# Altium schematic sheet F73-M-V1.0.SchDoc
size A3
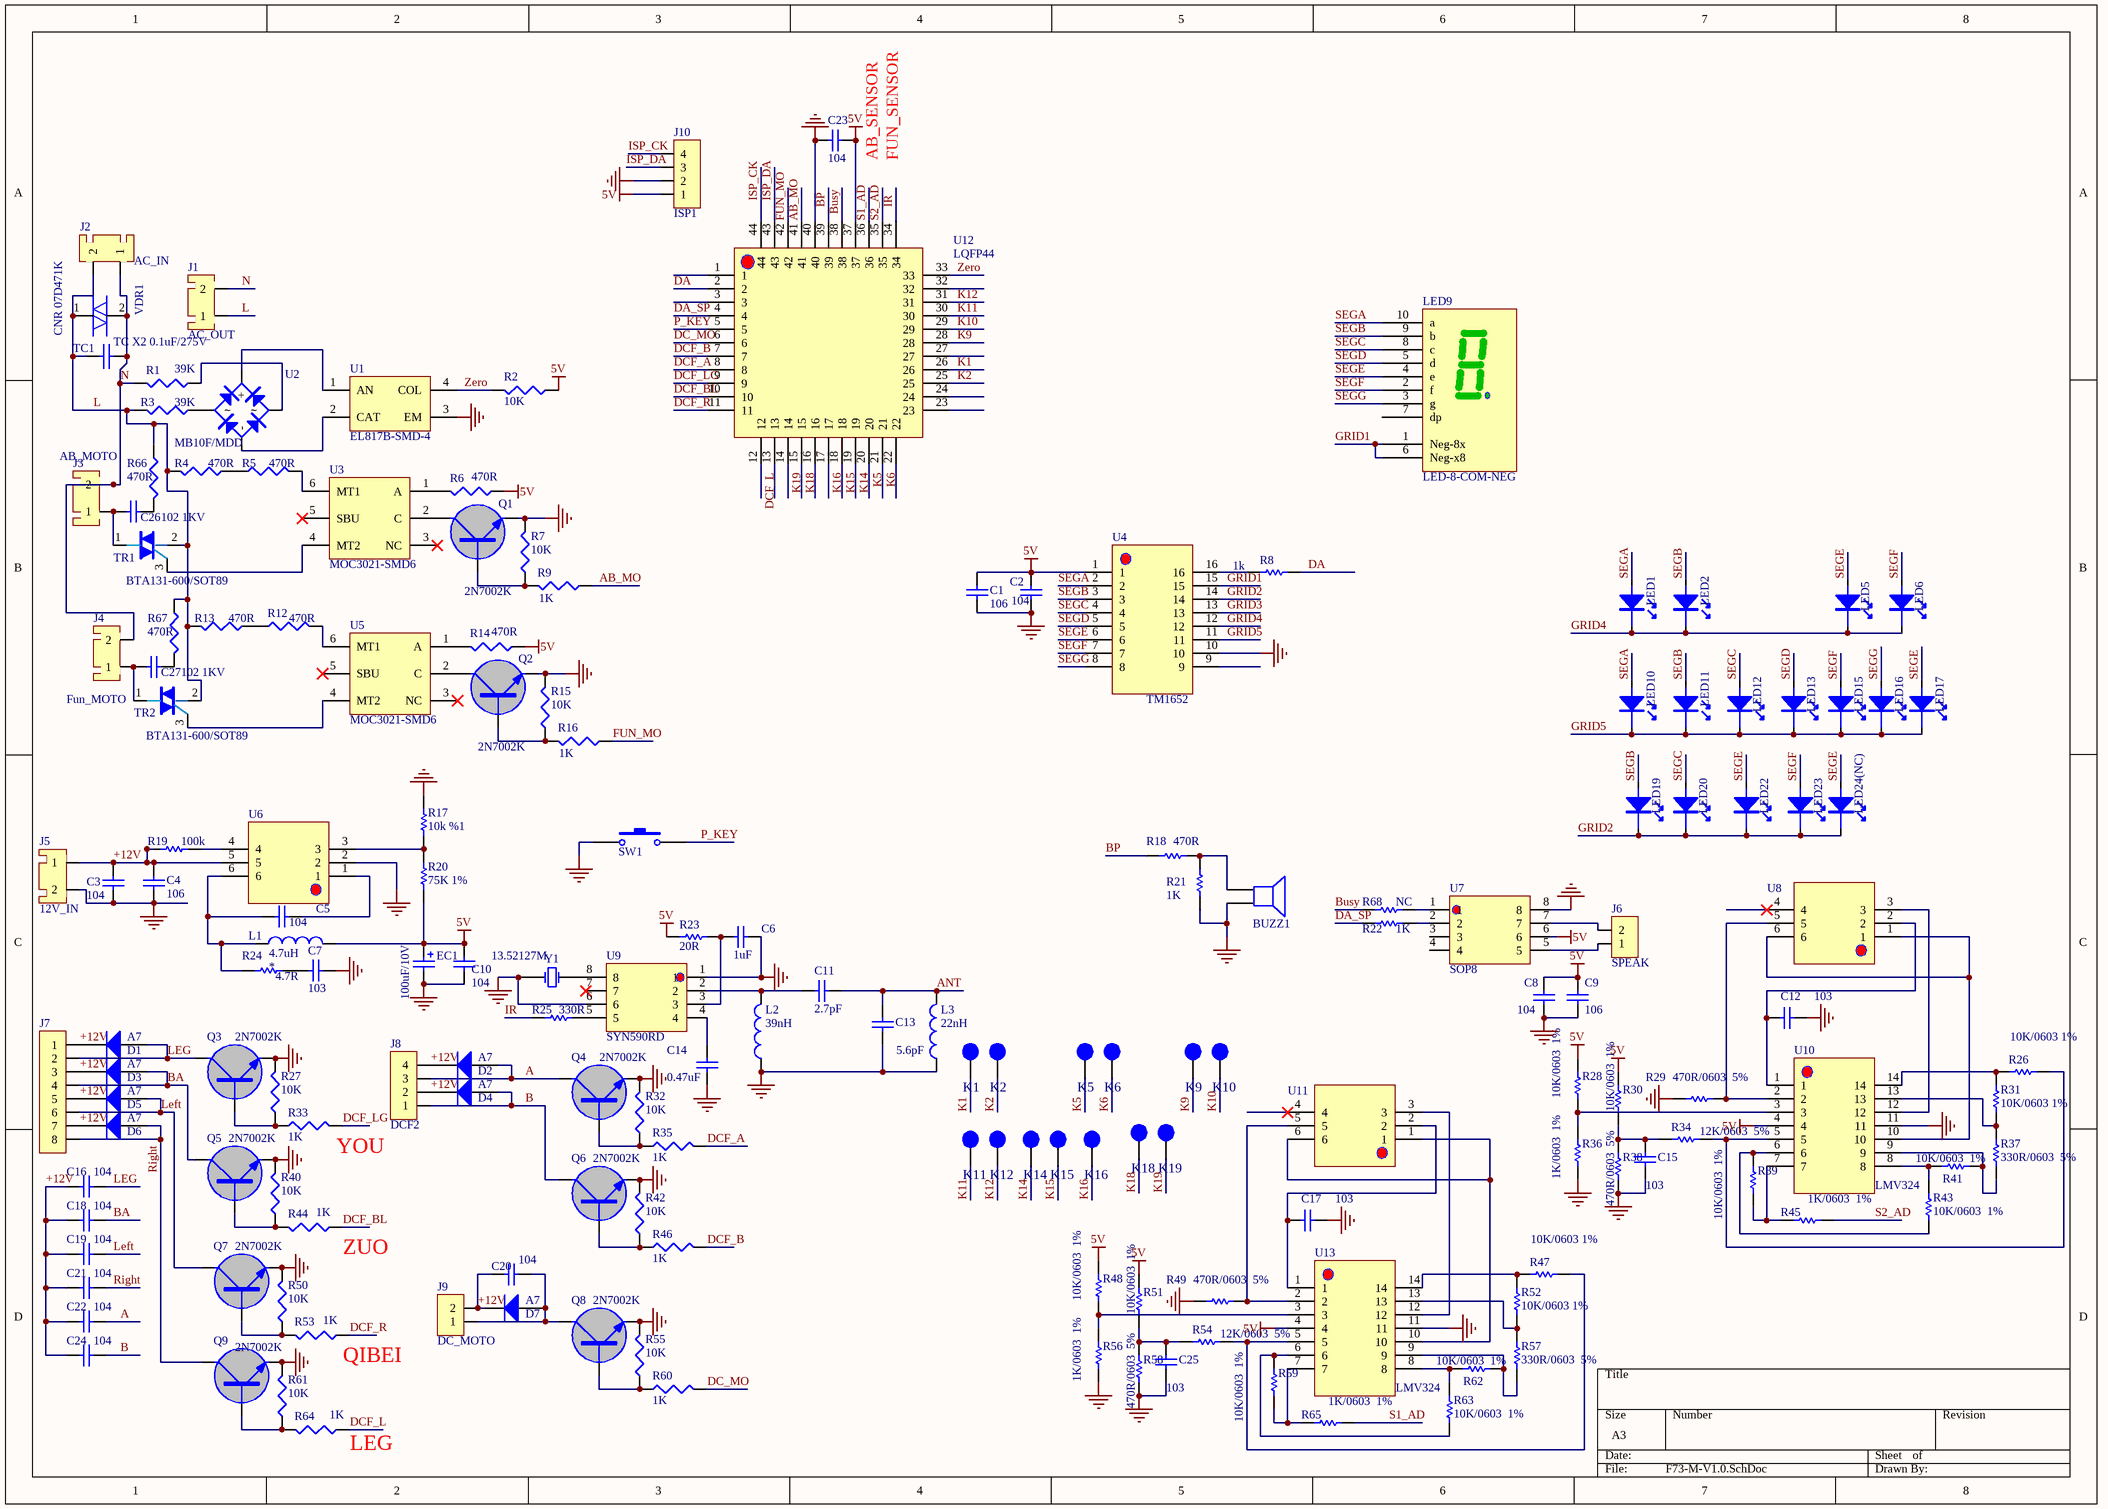
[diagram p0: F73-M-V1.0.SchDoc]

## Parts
BUZZ1  Speaker  [BUZ-1407-7.5]  (value not drawn)
C1  106  [0805C]
C2  104  [0603C]
C3  104  [0603C]
C4  106  [0805C]
C5  104  [0603C]
C6  1uF  [0603C]
C7  103  [0603C]
C8  104  [0603C]
C9  106  [0805C]
C10  104  [0603C]
C11  2.7pF  [0603C]
C12  103  [0603C]
C13  5.6pF  [0603C]
C14  0.47uF  [0603C]
C15  103  [0603C]
C16  104  [0603C]
C17  103  [0603C]
C18  104  [0603C]
C19  104  [0603C]
C20  104  [0603C]
C21  104  [0603C]
C22  104  [0603C]
C23  104  [0603C]
C24  104  [0603C]
C25  103  [0603C]
C26  102 1KV  [1206C]
C27  102 1KV  [1206C]
D1  A7  [SOD-123FL_L2.8-W1.8-LS3.7]
D2  A7  [SOD-123FL_L2.8-W1.8-LS3.7]
D3  A7  [SOD-123FL_L2.8-W1.8-LS3.7]
D4  A7  [SOD-123FL_L2.8-W1.8-LS3.7]
D5  A7  [SOD-123FL_L2.8-W1.8-LS3.7]
D6  A7  [SOD-123FL_L2.8-W1.8-LS3.7]
D7  A7  [SOD-123FL_L2.8-W1.8-LS3.7]
EC1  100uF/10V  [CAP SMD 6.3*5.5mm]
J1  AC_OUT  [K-VH3.96-3P]
J2  AC_IN  [K-VH3.96-3P]
J3  AB_MOTO  [K-VH3.96-3P]
J4  Fun_MOTO  [K-VH3.96-3P]
J5  12V_IN  [CON2-SMD-XHB 2*2.5MM]
J6  SPEAK  [CON2-SMD_PH2.0-1X2PW]
J7  (no value)  [CON8-SMD-XHB 8*2.5MM]
J8  DCF2  [CON4-SMD_4P-P2.54_XH2.54-4AB]
J9  DC_MOTO  [CON2-SMD-XHB 2*2.5MM]
J10  ISP1  [CON4 -2.54-H]
K1  Φ15 H8mm弹簧  [TK_HF-13*13*8]  (value not drawn)
K2  Φ15 H8mm弹簧  [TK_HF-13*13*8]  (value not drawn)
K5  Φ15 H8mm弹簧  [TK_HF-13*13*8]  (value not drawn)
K6  Φ15 H8mm弹簧  [TK_HF-13*13*8]  (value not drawn)
K9  Φ15 H8mm弹簧  [TK_HF-13*13*8]  (value not drawn)
K10  Φ15 H8mm弹簧  [TK_HF-13*13*8]  (value not drawn)
K11  Φ15 H8mm弹簧  [TK_HF-13*13*8]  (value not drawn)
K12  Φ15 H8mm弹簧  [TK_HF-13*13*8]  (value not drawn)
K14  Φ15 H8mm弹簧  [TK_HF-13*13*8]  (value not drawn)
K15  Φ15 H8mm弹簧  [TK_HF-13*13*8]  (value not drawn)
K16  Φ15 H8mm弹簧  [TK_HF-13*13*8]  (value not drawn)
K18  Φ15 H8mm弹簧  [TK_HF-13*13*8]  (value not drawn)
K19  Φ15 H8mm弹簧  [TK_HF-13*13*8]  (value not drawn)
L1  4.7uH  [INDC5050]
L2  39nH  [0603R]
L3  22nH  [0603R]
LED1  LED_0603  [LED_0603]  (value not drawn)
LED2  LED_0603  [LED_0603]  (value not drawn)
LED5  LED_0603  [LED_0603]  (value not drawn)
LED6  LED_0603  [LED_0603]  (value not drawn)
LED9  LED-8-COM-NEG  [LED1B-10P(7.5*14*H8.5 P2.54*10.16)]
LED10  LED_0603  [LED_0603]  (value not drawn)
LED11  LED_0603  [LED_0603]  (value not drawn)
LED12  LED_0603  [LED_0603]  (value not drawn)
LED13  LED_0603  [LED_0603]  (value not drawn)
LED15  LED_0603  [LED_0603]  (value not drawn)
LED16  LED_0603  [LED_0603]  (value not drawn)
LED17  LED_0603  [LED_0603]  (value not drawn)
LED19  LED_0603  [LED_0603]  (value not drawn)
LED20  LED_0603  [LED_0603]  (value not drawn)
LED22  LED_0603  [LED_0603]  (value not drawn)
LED23  LED_0603  [LED_0603]  (value not drawn)
LED24(NC)  LED_0603  [LED_0603]  (value not drawn)
Q1  2N7002K  [SOT-23 - MOS]
Q2  2N7002K  [SOT-23 - MOS]
Q3  2N7002K  [SOT-23 - MOS]
Q4  2N7002K  [SOT-23 - MOS]
Q5  2N7002K  [SOT-23 - MOS]
Q6  2N7002K  [SOT-23 - MOS]
Q7  2N7002K  [SOT-23 - MOS]
Q8  2N7002K  [SOT-23 - MOS]
Q9  2N7002K  [SOT-23 - MOS]
R1  39K  [1206R]
R2  10K  [0603]
R3  39K  [1206R]
R4  470R  [1206R]
R5  470R  [1206R]
R6  470R  [0603]
R7  10K  [0603]
R8  1k  [0603R]
R9  1K  [0603]
R12  470R  [1206R]
R13  470R  [1206R]
R14  470R  [0603]
R15  10K  [0603]
R16  1K  [0603]
R17  10k %1  [0603R]
R18  470R  [0603R]
R19  100k  [0603R]
R20  75K 1%  [0603R]
R21  1K  [0603R]
R22  1K  [0603R]
R23  20R  [0603R]
R24  4.7R  [0603R]
R25  330R  [0603R]
R26  10K/0603 1%  [0603R]
R27  10K  [0603]
R28  10K/0603  1%  [0603R]
R29  470R/0603  5%  [0603R]
R30  10K/0603  1%  [0603R]
R31  10K/0603 1%  [0603R]
R32  10K  [0603]
R33  1K  [0603]
R34  12K/0603  5%  [0603R]
R35  1K  [0603]
R36  1K/0603  1%  [0603R]
R37  330R/0603  5%  [0603R]
R38  470R/0603  5%  [0603R]
R39  10K/0603  1%  [0603R]
R40  10K  [0603]
R41  10K/0603  1%  [0603R]
R42  10K  [0603]
R43  10K/0603  1%  [0603R]
R44  1K  [0603]
R45  1K/0603  1%  [0603R]
R46  1K  [0603]
R47  10K/0603 1%  [0603R]
R48  10K/0603  1%  [0603R]
R49  470R/0603  5%  [0603R]
R50  10K  [0603]
R51  10K/0603  1%  [0603R]
R52  10K/0603 1%  [0603R]
R53  1K  [0603]
R54  12K/0603  5%  [0603R]
R55  10K  [0603]
R56  1K/0603  1%  [0603R]
R57  330R/0603  5%  [0603R]
R58  470R/0603  5%  [0603R]
R59  10K/0603  1%  [0603R]
R60  1K  [0603]
R61  10K  [0603]
R62  10K/0603  1%  [0603R]
R63  10K/0603  1%  [0603R]
R64  1K  [0603]
R65  1K/0603  1%  [0603R]
R66  470R  [1206R]
R67  470R  [1206R]
R68  NC  [0603R]
SW1  SW-PB  [BUTTON-SMD-6*6*10]  (value not drawn)
TC1  TC X2 0.1uF/275V  [CAP-TH_L13.0-W6.0-P10.00-D0.6]
TR1  BTA131-600/SOT89  [SOT-89 BT131-600]
TR2  BTA131-600/SOT89  [SOT-89 BT131-600]
U1  EL817B-SMD-4  [PC817-smd]
U2  MB10F/MDD  [DB-MB10F]
U3  MOC3021-SMD6  [SMD6]
U4  TM1652  [SOP16(150MIL)]
U5  MOC3021-SMD6  [SMD6]
U6  HT7712  [SOT23-6_M]  (value not drawn)
U7  SOP8  [SOP8-SS]
U8  SOP6  [PSG010R/S]  (value not drawn)
U9  SYN590RD  [SOP8(5.1*6.2mm)]
U10  LMV324  [SOP14(150mil)]
U11  SOP6  [PSG010R/S]  (value not drawn)
U12  LQFP44  [LQFP44]
U13  LMV324  [SOP14(150mil)]
VDR1  CNR 07D471K  [RES-TH_L9.0-W5.0-P5-D0.7-S3.00]
Y1  13.52127M  [HC-49S_L11.4-W4.8]

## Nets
5V: C1.2 C2.2 C8.1 C9.1 C10.1 C23.1 EC1.1 J10.1 L1.2 R2.1 R6.1 R14.1 R20.1 R23.1 R28.1 R30.1 R48.1 R51.1 U4.1 U7.6 U10.4 U12.37 U13.4
GND: BUZZ1.1 C1.1 C2.1 C3.2 C4.2 C6.2 C7.1 C8.2 C9.2 C10.2 C12.1 C13.1 C14.2 C15.1 C17.1 C23.2 C25.1 EC1.2 J5.2 J10.2 L2.1 L3.1 Q1.E Q2.E Q3.E Q4.E Q5.E Q6.E Q7.E Q8.E Q9.E R7.2 R15.2 R17.2 R21.2 R27.2 R29.2 R32.2 R36.2 R38.2 R40.2 R42.2 R49.2 R50.2 R55.2 R56.2 R58.2 R61.2 SW1.1 U1.3(EM) U4.10 U6.2 U7.8 U9.1 U9.6 U10.11 U12.40 U13.11 Y1.2(OSC2)
+12V: C3.1 C4.1 C16.1 C18.1 C19.1 C20.1 C21.1 C22.1 C24.1 D1.2(K) D2.2(K) D3.2(K) D4.2(K) D5.2(K) D6.2(K) D7.2(K) J5.1 J7.1 J7.3 J7.5 J7.7 J8.2 J8.4 J9.2 R19.1 U6.5
A: C22.2 D2.1(A) J8.3 Q4.C
AB_MO: R9.1 U12.41
ANT: C11.1 C13.2 L3.2
B: C24.2 D4.1(A) J8.1 Q6.C
BA: C18.2 D3.1(A) J7.4 Q5.C
BP: R18.2 U12.39
Busy: R68.1 U12.38
DA: R8.1 U12.2
DA_SP: R22.1 U12.4
DC_MO: R60.2 U12.6
DCF_A: R35.2 U12.8
DCF_B: R46.2 U12.7
DCF_BL: R44.1 U12.10
DCF_L: R64.1 U12.12
DCF_LG: R33.2 U12.9
DCF_R: R53.1 U12.11
FUN_MO: R16.1 U12.42
GRID1: LED9.1(Neg-8x) LED9.6(Neg-x8) U4.15
GRID2: LED19.2 LED20.2 LED22.2 LED23.2 LED24(NC).2 U4.14
GRID3: U4.13
GRID4: LED1.2 LED2.2 LED5.2 LED6.2 U4.12
GRID5: LED10.2 LED11.2 LED12.2 LED13.2 LED15.2 LED16.2 LED17.2 U4.11
IR: R25.1 U12.34
ISP_CK: J10.4 U12.44
ISP_DA: J10.3 U12.43
K1: K1.2 U12.26
K2: K2.2 U12.25
K5: K5.2 U12.20
K6: K6.2 U12.21
K9: K9.2 U12.28
K10: K10.2 U12.29
K11: K11.2 U12.30
K12: K12.2 U12.31
K14: K14.2 U12.19
K15: K15.2 U12.18
K16: K16.2 U12.17
K18: K18.2 U12.15
K19: K19.2 U12.14
L: J1.1 J2.2 R3.2 R4.2 R13.2 R66.1 R67.1 TC1.2 TR1.2 TR2.2 VDR1.1
Left: C19.2 D5.1(A) J7.6 Q7.C
LEG: C16.2 D1.1(A) J7.2 Q3.C
N: J1.2 J2.1 J3.2 J4.2 R1.2 TC1.1 VDR1.2
P_KEY: SW1.2 U12.5
Right: C21.2 D6.1(A) J7.8 Q9.C
S1_AD: R65.1 U12.36
S2_AD: R45.1 U12.35
SEGA: LED1.1 LED9.10(a) LED10.1 U4.2
SEGB: LED2.1 LED9.9(b) LED11.1 LED19.1 U4.3
SEGC: LED9.8(c) LED12.1 LED20.1 U4.4
SEGD: LED9.5(d) LED13.1 U4.5
SEGE: LED5.1 LED9.4(e) LED17.1 LED22.1 LED24(NC).1 U4.6
SEGF: LED6.1 LED9.2(f) LED15.1 LED23.1 U4.7
SEGG: LED9.3(g) LED16.1 U4.8
Zero: R2.2 U1.4(COL) U12.33
NetBUZZ1_2: BUZZ1.2 R18.1 R21.1
NetC5_1: C5.1 U6.1
NetC5_2: C5.2 L1.1 R24.2 U6.6
NetC6_1: C6.1 R23.2 U9.3
NetC7_2: C7.2 R24.1
NetC11_2: C11.2 L2.2 U9.2
NetC12_2: C12.2 U8.2 U10.1
NetC14_1: C14.1 U9.4
NetC15_2: C15.2 R30.2 R34.2 R38.1
NetC17_2: C17.2 U11.2 U13.1
NetC20_2: C20.2 D7.1(A) J9.1 Q8.C
NetC25_2: C25.2 R51.2 R54.2 R58.1
NetC26_1: C26.1 R66.2
NetC26_2: C26.2 J3.1 TR1.1
NetC27_1: C27.1 R67.2
NetC27_2: C27.2 J4.1 TR2.1
NetJ6_1: J6.1 U7.5
NetJ6_2: J6.2 U7.7
NetQ1_B: Q1.B R7.1 R9.2
NetQ1_C: Q1.C U3.2(C)
NetQ2_B: Q2.B R15.1 R16.2
NetQ2_C: Q2.C U5.2(C)
NetQ3_B: Q3.B R27.1 R33.1
NetQ4_B: Q4.B R32.1 R35.1
NetQ5_B: Q5.B R40.1 R44.2
NetQ6_B: Q6.B R42.1 R46.1
NetQ7_B: Q7.B R50.1 R53.2
NetQ8_B: Q8.B R55.1 R60.1
NetQ9_B: Q9.B R61.1 R64.2
NetR1_1: R1.1 U2.AC2(～)
NetR3_1: R3.1 U2.AC1(～)
NetR4_1: R4.1 R5.1
NetR5_2: R5.2 U3.6(MT1)
NetR6_2: R6.2 U3.1(A)
NetR8_2: R8.2 U4.16
NetR12_1: R12.1 R13.1
NetR12_2: R12.2 U5.6(MT1)
NetR14_2: R14.2 U5.1(A)
NetR17_1: R17.1 R20.2 U6.3
NetR19_2: R19.2 U6.4
NetR22_2: R22.2 U7.2
NetR25_2: R25.2 U9.5
NetR26_1: R26.1 R31.1 U10.14
NetR26_2: R26.2 R34.1 U10.5
NetR28_2: R28.2 R36.1 U10.3
NetR29_1: R29.1 U8.5 U10.2
NetR31_2: R31.2 R37.1 U10.13
NetR37_2: R37.2 R41.2 U10.9
NetR39_1: R39.1 R43.2 U10.6
NetR39_2: R39.2 R45.2 U10.7
NetR41_1: R41.1 R43.1 U10.8
NetR47_1: R47.1 R52.1 U13.14
NetR47_2: R47.2 R54.1 U13.5
NetR48_2: R48.2 R56.1 U13.3
NetR49_1: R49.1 U11.5 U13.2
NetR52_2: R52.2 R57.1 U13.13
NetR57_2: R57.2 R62.2 U13.9
NetR59_1: R59.1 R63.2 U13.6
NetR59_2: R59.2 R65.2 U13.7
NetR62_1: R62.1 R63.1 U13.8
NetR68_2: R68.2 U7.1
NetTR1_3: TR1.3 U3.4(MT2)
NetTR2_3: TR2.3 U5.4(MT2)
NetU1_1: U1.1(AN) U2.V+(+)
NetU1_2: U1.2(CAT) U2.V-(-)
NetU8_1: U8.1 U8.6 U10.10
NetU8_3: U8.3 U10.12
NetU9_8: U9.8 Y1.1(OSC1)
NetU11_1: U11.1 U11.6 U13.10
NetU11_3: U11.3 U13.12

Not connected (* = marked no-connect by the designer): LED9 7(dp); U3 3(NC)* 5(SBU)*; U4 9; U5 3(NC)* 5(SBU)*; U7 3 4; U8 4*; U9 7*; U11 4*; U12 1 3 13 16 22 23 24 27 32

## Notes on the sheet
- (near C23) AB_SENSOR
- (near C23) FUN_SENSOR
- (near R33) YOU
- (near R44) ZUO
- (near R53) QIBEI
- (near R64) LEG

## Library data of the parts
BUZZ1 = Speaker: Loudspeaker; Manufacturer: Generic Components
C1 C2 C4 C5 C8-C10 C20 C26 C27 = Cap: Capacitor; Manufacturer: Generic Components; Class: Passive; Value: 100pF
C3 C7 C12 C15-C19 C21-C25 = Cap: Capacitor; Value: 0
C6 C11 C13 C14 = Cap: Capacitor; Value: 104
D1-D7 = Diode 1N4007: 1 Amp General Purpose Rectifier
EC1 = Cap Pol1: Polarized Capacitor (Radial); Manufacturer: Generic Components; Class: Passive; Value: 100pF
J1-J4 = PITCH3.96-5.0-2A
J5 = PITCH2.5-2A
J6 J9 = CON2
J7 = CON8
J8 J10 = CON4
K1 K2 K5 K6 K9-K12 K14-K16 K18 K19 = TOUCH-PAD
L1-L3 = Inductor: Code_IEC: 1005
LED1 LED2 LED5 LED6 LED10-LED13 LED15-LED17 LED19 LED20 LED22 LED23 LED24(NC) = LED
Q1-Q9 = NPN-8050-BCE-25V/500mA
R1 R3-R5 R12 R13 R66 R67 = 1Ω±1%/0805-1206
R2 R6 R7 R9 R14-R16 R27 R32 R33 R35 R40 R42 R44 R46 R50 R53 R55 R60 R61 R64 = 1Ω±1%/0603-0805
R8 R17-R26 R28-R31 R34 R36-R39 R41 R43 R45 R47-R49 R51 R52 R54 R56-R59 R62 R63 R65 R68 = Res1: Resistor; Value: 0
SW1 = SW-PB: Switch
TC1 = CAP1
TR1 TR2 = Triac
U1 = EL817-DIP-4
U2 = BD-ABS10/MB10S: Diode Bridge
U3 U5 = MOC3021-DIP-6
U4 = SOP16
U6 = SOP6
U9 = SOP8
U10 U13 = SOP14
VDR1 = VAR
Y1 = XTAL: Crystal Oscillator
